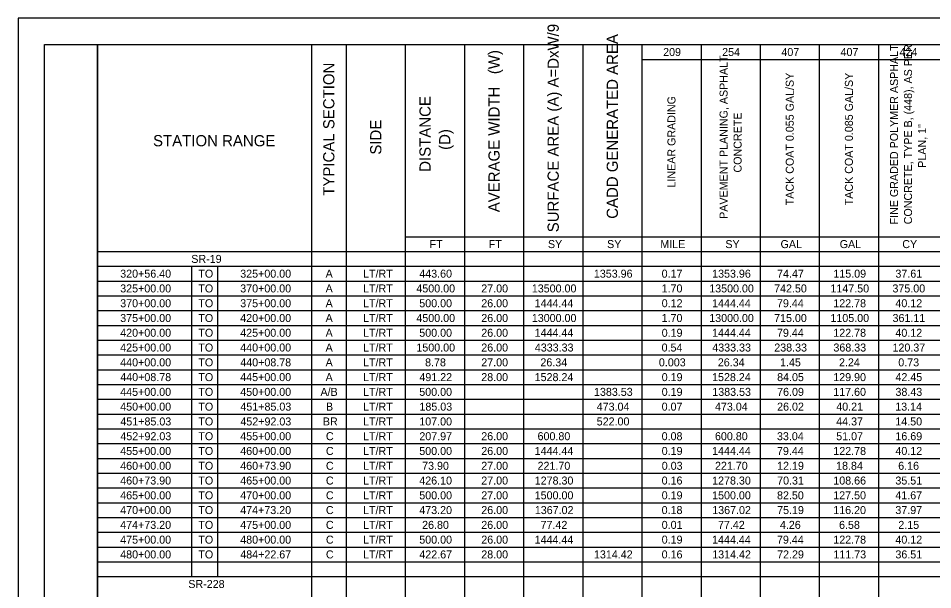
# Model space of a CAD drawing. Extents: x 0 to 34, y 0 to 22.
# Drawn here: x 0 to 17.33, y 11.16 to 22 of the extents above; entities that cross this region are included whole.
import ezdxf

# ---------------------------------------------------------------- set-up
doc = ezdxf.new("R2010")
doc.units = 0
for name, color, linetype in [('SH_Border', 7, 'Continuous'), ('SH_Cut_Line', 7, 'Continuous'), ('SH_Text', 7, 'Continuous')]:
    doc.layers.add(name, color=color, linetype=linetype)

msp = doc.modelspace()

# ---------------------------------------------------------------- linework, layer by layer
at = {"layer": 'SH_Border'}
for points in [[(0.5, 21.5), (1.5, 21.5), (1.5, 0.5), (0.5, 0.5)], [(1.5, 21.5), (33.5, 21.5), (33.5, 0.5), (1.5, 0.5)]]:
    msp.add_lwpolyline(points, close=True, dxfattribs=at)
at = {"layer": 'SH_Cut_Line'}
msp.add_lwpolyline([(0, 0), (34, 0), (34, 22), (0, 22)], close=True, dxfattribs=at)
at = {"layer": 'SH_Text'}
for p, q in [((1.5, 21.5), (32, 21.5)), ((1.5, 21.5), (1.5, 0.513)), ((5.556, 21.5), (5.556, 1.04)), ((6.215, 21.5), (6.215, 1.04)), ((7.336, 21.5), (7.336, 1.04)), ((8.457, 21.5), (8.457, 1.04)), ((9.578, 21.5), (9.578, 1.04)), ((10.699, 21.5), (10.699, 1.04)), ((11.821, 21.5), (11.821, 0.513)), ((12.942, 21.5), (12.942, 0.513)), ((14.063, 21.5), (14.063, 0.513)), ((15.184, 21.5), (15.184, 0.513)), ((16.305, 21.5), (16.305, 0.513)), ((11.821, 21.22), (32, 21.22)), ((7.336, 17.856), (32, 17.856)), ((1.5, 17.576), (32, 17.576)), ((1.5, 17.296), (32, 17.296)), ((3.281, 17.296), (3.281, 11.41)), ((3.775, 17.296), (3.775, 11.41)), ((1.5, 17.016), (32, 17.016)), ((1.5, 16.735), (32, 16.735)), ((1.5, 16.455), (32, 16.455)), ((1.5, 16.175), (32, 16.175)), ((1.5, 15.895), (32, 15.895)), ((1.5, 15.614), (32, 15.614)), ((1.5, 15.334), (32, 15.334)), ((1.5, 15.054), (32, 15.054)), ((1.5, 14.774), (32, 14.774)), ((1.5, 14.493), (32, 14.493)), ((1.5, 14.213), (32, 14.213)), ((1.5, 13.933), (32, 13.933)), ((1.5, 13.652), (32, 13.652)), ((1.5, 13.372), (32, 13.372)), ((1.5, 13.092), (32, 13.092)), ((1.5, 12.812), (32, 12.812)), ((1.5, 12.531), (32, 12.531)), ((1.5, 12.251), (32, 12.251)), ((1.5, 11.971), (32, 11.971)), ((1.5, 11.691), (32, 11.691)), ((1.5, 11.41), (32, 11.41))]:
    msp.add_line(p, q, dxfattribs=at)

# ---------------------------------------------------------------- texts
for s, height, p in [('SURFACE AREA (A) A=DxW/9', 0.21235, (10.245, 17.941)), ('CADD GENERATED AREA', 0.21235, (11.366, 18.197)), ('FINE GRADED POLYMER ASPHALT ', 0.15168, (16.676, 18.09)), ('CONCRETE, TYPE B, (448), AS PER ', 0.15168, (16.941, 18.092)), ('AVERAGE WIDTH   (W)', 0.21235, (9.124, 18.321)), ('PAVEMENT PLANING, ASPHALT ', 0.15168, (13.445, 18.196)), ('TYPICAL SECTION', 0.21235, (5.992, 18.634)), ('TACK COAT 0.055 GAL/SY', 0.15168, (14.699, 18.453)), ('TACK COAT 0.085 GAL/SY', 0.15168, (15.82, 18.453)), ('DISTANCE                                                                                                        ', 0.212346, (7.817, 19.088)), ('LINEAR GRADING', 0.15168, (12.457, 18.789)), ('CONCRETE', 0.1517, (13.711, 19.074)), ('SIDE', 0.2123, (6.882, 19.413)), ('PLAN, 1"', 0.1517, (17.207, 19.165)), ('(D)', 0.2123, (8.189, 19.504))]:
    msp.add_text(s, height=height, rotation=90, dxfattribs=at).set_placement(p)
for s, height, p in [('209', 0.1517, (12.223, 21.284)), ('254', 0.1517, (13.342, 21.284)), ('407', 0.1517, (14.465, 21.284)), ('407', 0.1517, (15.586, 21.284)), ('424', 0.1517, (16.705, 21.284)), ('STATION RANGE', 0.21235, (2.554, 19.572)), ('FT', 0.1517, (7.796, 17.641)), ('FT', 0.1517, (8.917, 17.641)), ('SY', 0.1517, (10.04, 17.641)), ('SY', 0.1517, (11.161, 17.641)), ('MILE', 0.1517, (12.17, 17.641)), ('SY', 0.1517, (13.403, 17.641)), ('GAL', 0.1517, (14.449, 17.641)), ('GAL', 0.1517, (15.57, 17.641)), ('CY', 0.1517, (16.757, 17.641)), ('SR-19', 0.1517, (3.279, 17.36)), ('320+56.40', 0.1517, (1.932, 17.08)), ('TO', 0.1517, (3.413, 17.08)), ('325+00.00', 0.1517, (4.207, 17.08)), ('A', 0.152, (5.825, 17.08)), ('LT/RT', 0.1517, (6.535, 17.08)), ('443.60', 0.1517, (7.601, 17.08)), ('1353.96', 0.1517, (10.91, 17.08)), ('0.17', 0.1517, (12.195, 17.08)), ('1353.96', 0.1517, (13.152, 17.08)), ('74.47', 0.1517, (14.383, 17.08)), ('115.09', 0.1517, (15.45, 17.08)), ('37.61', 0.1517, (16.626, 17.08)), ('325+00.00', 0.1517, (1.932, 16.8)), ('TO', 0.1517, (3.413, 16.8)), ('370+00.00', 0.1517, (4.207, 16.8)), ('A', 0.152, (5.825, 16.8)), ('LT/RT', 0.1517, (6.535, 16.8)), ('4500.00', 0.1517, (7.546, 16.8)), ('27.00', 0.1517, (8.776, 16.8)), ('13500.00', 0.1517, (9.734, 16.8)), ('1.70', 0.1517, (12.194, 16.8)), ('13500.00', 0.1517, (13.097, 16.8)), ('742.50', 0.1517, (14.327, 16.8)), ('1147.50', 0.1517, (15.394, 16.8)), ('375.00', 0.1517, (16.57, 16.8)), ('370+00.00', 0.1517, (1.932, 16.519)), ('TO', 0.1517, (3.413, 16.519)), ('375+00.00', 0.1517, (4.207, 16.519)), ('A', 0.152, (5.825, 16.519)), ('LT/RT', 0.1517, (6.535, 16.519)), ('500.00', 0.1517, (7.601, 16.519)), ('26.00', 0.1517, (8.776, 16.519)), ('1444.44', 0.1517, (9.788, 16.519)), ('0.12', 0.1517, (12.196, 16.519)), ('1444.44', 0.1517, (13.151, 16.519)), ('79.44', 0.1517, (14.381, 16.519)), ('122.78', 0.1517, (15.449, 16.519)), ('40.12', 0.1517, (16.626, 16.519)), ('375+00.00', 0.1517, (1.932, 16.239)), ('TO', 0.1517, (3.413, 16.239)), ('420+00.00', 0.1517, (4.207, 16.239)), ('A', 0.152, (5.825, 16.239)), ('LT/RT', 0.1517, (6.535, 16.239)), ('4500.00', 0.1517, (7.546, 16.239)), ('26.00', 0.1517, (8.776, 16.239)), ('13000.00', 0.1517, (9.734, 16.239)), ('1.70', 0.1517, (12.194, 16.239)), ('13000.00', 0.1517, (13.097, 16.239)), ('715.00', 0.1517, (14.327, 16.239)), ('1105.00', 0.1517, (15.394, 16.239)), ('361.11', 0.1517, (16.572, 16.239)), ('420+00.00', 0.1517, (1.932, 15.959)), ('TO', 0.1517, (3.413, 15.959)), ('425+00.00', 0.1517, (4.207, 15.959)), ('A', 0.152, (5.825, 15.959)), ('LT/RT', 0.1517, (6.535, 15.959)), ('500.00', 0.1517, (7.601, 15.959)), ('26.00', 0.1517, (8.776, 15.959)), ('1444.44', 0.1517, (9.788, 15.959)), ('0.19', 0.1517, (12.196, 15.959)), ('1444.44', 0.1517, (13.151, 15.959)), ('79.44', 0.1517, (14.381, 15.959)), ('122.78', 0.1517, (15.449, 15.959)), ('40.12', 0.1517, (16.626, 15.959)), ('425+00.00', 0.1517, (1.932, 15.679)), ('TO', 0.1517, (3.413, 15.679)), ('440+00.00', 0.1517, (4.207, 15.679)), ('A', 0.152, (5.825, 15.679)), ('LT/RT', 0.1517, (6.535, 15.679)), ('1500.00', 0.1517, (7.546, 15.679)), ('26.00', 0.1517, (8.776, 15.679)), ('4333.33', 0.1517, (9.791, 15.679)), ('0.54', 0.1517, (12.194, 15.679)), ('4333.33', 0.1517, (13.155, 15.679)), ('238.33', 0.1517, (14.33, 15.679)), ('368.33', 0.1517, (15.451, 15.679)), ('120.37', 0.1517, (16.571, 15.679)), ('440+00.00', 0.1517, (1.932, 15.398)), ('TO', 0.1517, (3.413, 15.398)), ('440+08.78', 0.1517, (4.208, 15.398)), ('A', 0.152, (5.825, 15.398)), ('LT/RT', 0.1517, (6.535, 15.398)), ('8.78', 0.1517, (7.711, 15.398)), ('27.00', 0.1517, (8.776, 15.398)), ('26.34', 0.1517, (9.897, 15.398)), ('0.003', 0.1517, (12.143, 15.398)), ('26.34', 0.1517, (13.26, 15.398)), ('1.45', 0.1517, (14.439, 15.398)), ('2.24', 0.1517, (15.557, 15.398)), ('0.73', 0.1517, (16.681, 15.398)), ('440+08.78', 0.1517, (1.933, 15.118)), ('TO', 0.1517, (3.413, 15.118)), ('445+00.00', 0.1517, (4.207, 15.118)), ('A', 0.152, (5.825, 15.118)), ('LT/RT', 0.1517, (6.535, 15.118)), ('491.22', 0.1517, (7.603, 15.118)), ('28.00', 0.1517, (8.776, 15.118)), ('1528.24', 0.1517, (9.788, 15.118)), ('0.19', 0.1517, (12.196, 15.118)), ('1528.24', 0.1517, (13.151, 15.118)), ('84.05', 0.1517, (14.384, 15.118)), ('129.90', 0.1517, (15.448, 15.118)), ('42.45', 0.1517, (16.627, 15.118)), ('445+00.00', 0.1517, (1.932, 14.838)), ('TO', 0.1517, (3.413, 14.838)), ('450+00.00', 0.1517, (4.207, 14.838)), ('A/B', 0.1517, (5.728, 14.838)), ('LT/RT', 0.1517, (6.535, 14.838)), ('500.00', 0.1517, (7.601, 14.838)), ('1383.53', 0.1517, (10.913, 14.838)), ('0.19', 0.1517, (12.196, 14.838)), ('1383.53', 0.1517, (13.155, 14.838)), ('76.09', 0.1517, (14.384, 14.838)), ('117.60', 0.1517, (15.448, 14.838)), ('38.43', 0.1517, (16.627, 14.838)), ('450+00.00', 0.1517, (1.932, 14.558)), ('TO', 0.1517, (3.413, 14.558)), ('451+85.03', 0.1517, (4.21, 14.558)), ('B', 0.152, (5.832, 14.558)), ('LT/RT', 0.1517, (6.535, 14.558)), ('185.03', 0.1517, (7.604, 14.558)), ('473.04', 0.1517, (10.964, 14.558)), ('0.07', 0.1517, (12.195, 14.558)), ('473.04', 0.1517, (13.206, 14.558)), ('26.02', 0.1517, (14.384, 14.558)), ('40.21', 0.1517, (15.505, 14.558)), ('13.14', 0.1517, (16.623, 14.558)), ('451+85.03', 0.1517, (1.935, 14.277)), ('TO', 0.1517, (3.413, 14.277)), ('452+92.03', 0.1517, (4.21, 14.277)), ('BR', 0.1517, (5.773, 14.277)), ('LT/RT', 0.1517, (6.535, 14.277)), ('107.00', 0.1517, (7.601, 14.277)), ('522.00', 0.1517, (10.964, 14.277)), ('44.37', 0.1517, (15.504, 14.277)), ('14.50', 0.1517, (16.624, 14.277)), ('452+92.03', 0.1517, (1.935, 13.997)), ('TO', 0.1517, (3.413, 13.997)), ('455+00.00', 0.1517, (4.207, 13.997)), ('C', 0.152, (5.831, 13.997)), ('LT/RT', 0.1517, (6.535, 13.997)), ('207.97', 0.1517, (7.602, 13.997)), ('26.00', 0.1517, (8.776, 13.997)), ('600.80', 0.1517, (9.843, 13.997)), ('0.08', 0.1517, (12.195, 13.997)), ('600.80', 0.1517, (13.206, 13.997)), ('33.04', 0.1517, (14.381, 13.997)), ('51.07', 0.1517, (15.504, 13.997)), ('16.69', 0.1517, (16.626, 13.997)), ('455+00.00', 0.1517, (1.932, 13.717)), ('TO', 0.1517, (3.413, 13.717)), ('460+00.00', 0.1517, (4.207, 13.717)), ('C', 0.152, (5.831, 13.717)), ('LT/RT', 0.1517, (6.535, 13.717)), ('500.00', 0.1517, (7.601, 13.717)), ('26.00', 0.1517, (8.776, 13.717)), ('1444.44', 0.1517, (9.788, 13.717)), ('0.19', 0.1517, (12.196, 13.717)), ('1444.44', 0.1517, (13.151, 13.717)), ('79.44', 0.1517, (14.381, 13.717)), ('122.78', 0.1517, (15.449, 13.717)), ('40.12', 0.1517, (16.626, 13.717)), ('460+00.00', 0.1517, (1.932, 13.436)), ('TO', 0.1517, (3.413, 13.436)), ('460+73.90', 0.1517, (4.207, 13.436)), ('C', 0.152, (5.831, 13.436)), ('LT/RT', 0.1517, (6.535, 13.436)), ('73.90', 0.1517, (7.655, 13.436)), ('27.00', 0.1517, (8.776, 13.436)), ('221.70', 0.1517, (9.843, 13.436)), ('0.03', 0.1517, (12.197, 13.436)), ('221.70', 0.1517, (13.206, 13.436)), ('12.19', 0.1517, (14.384, 13.436)), ('18.84', 0.1517, (15.502, 13.436)), ('6.16', 0.1517, (16.679, 13.436)), ('460+73.90', 0.1517, (1.932, 13.156)), ('TO', 0.1517, (3.413, 13.156)), ('465+00.00', 0.1517, (4.207, 13.156)), ('C', 0.152, (5.831, 13.156)), ('LT/RT', 0.1517, (6.535, 13.156)), ('426.10', 0.1517, (7.601, 13.156)), ('27.00', 0.1517, (8.776, 13.156)), ('1278.30', 0.1517, (9.789, 13.156)), ('0.16', 0.1517, (12.195, 13.156)), ('1278.30', 0.1517, (13.152, 13.156)), ('70.31', 0.1517, (14.384, 13.156)), ('108.66', 0.1517, (15.449, 13.156)), ('35.51', 0.1517, (16.626, 13.156)), ('465+00.00', 0.1517, (1.932, 12.876)), ('TO', 0.1517, (3.413, 12.876)), ('470+00.00', 0.1517, (4.207, 12.876)), ('C', 0.152, (5.831, 12.876)), ('LT/RT', 0.1517, (6.535, 12.876)), ('500.00', 0.1517, (7.601, 12.876)), ('27.00', 0.1517, (8.776, 12.876)), ('1500.00', 0.1517, (9.789, 12.876)), ('0.19', 0.1517, (12.196, 12.876)), ('1500.00', 0.1517, (13.152, 12.876)), ('82.50', 0.1517, (14.382, 12.876)), ('127.50', 0.1517, (15.448, 12.876)), ('41.67', 0.1517, (16.625, 12.876)), ('470+00.00', 0.1517, (1.932, 12.596)), ('TO', 0.1517, (3.413, 12.596)), ('474+73.20', 0.1517, (4.207, 12.596)), ('C', 0.152, (5.831, 12.596)), ('LT/RT', 0.1517, (6.535, 12.596)), ('473.20', 0.1517, (7.601, 12.596)), ('26.00', 0.1517, (8.776, 12.596)), ('1367.02', 0.1517, (9.791, 12.596)), ('0.18', 0.1517, (12.195, 12.596)), ('1367.02', 0.1517, (13.154, 12.596)), ('75.19', 0.1517, (14.384, 12.596)), ('116.20', 0.1517, (15.448, 12.596)), ('37.97', 0.1517, (16.625, 12.596)), ('474+73.20', 0.1517, (1.932, 12.315)), ('TO', 0.1517, (3.413, 12.315)), ('475+00.00', 0.1517, (4.207, 12.315)), ('C', 0.152, (5.831, 12.315)), ('LT/RT', 0.1517, (6.535, 12.315)), ('26.80', 0.1517, (7.655, 12.315)), ('26.00', 0.1517, (8.776, 12.315)), ('77.42', 0.1517, (9.9, 12.315)), ('0.01', 0.1517, (12.196, 12.315)), ('77.42', 0.1517, (13.263, 12.315)), ('4.26', 0.1517, (14.437, 12.315)), ('6.58', 0.1517, (15.558, 12.315)), ('2.15', 0.1517, (16.681, 12.315)), ('475+00.00', 0.1517, (1.932, 12.035)), ('TO', 0.1517, (3.413, 12.035)), ('480+00.00', 0.1517, (4.207, 12.035)), ('C', 0.152, (5.831, 12.035)), ('LT/RT', 0.1517, (6.535, 12.035)), ('500.00', 0.1517, (7.601, 12.035)), ('26.00', 0.1517, (8.776, 12.035)), ('1444.44', 0.1517, (9.788, 12.035)), ('0.19', 0.1517, (12.196, 12.035)), ('1444.44', 0.1517, (13.151, 12.035)), ('79.44', 0.1517, (14.381, 12.035)), ('122.78', 0.1517, (15.449, 12.035)), ('40.12', 0.1517, (16.626, 12.035)), ('480+00.00', 0.1517, (1.932, 11.755)), ('TO', 0.1517, (3.413, 11.755)), ('484+22.67', 0.1517, (4.208, 11.755)), ('C', 0.152, (5.831, 11.755)), ('LT/RT', 0.1517, (6.535, 11.755)), ('422.67', 0.1517, (7.602, 11.755)), ('28.00', 0.1517, (8.776, 11.755)), ('1314.42', 0.1517, (10.912, 11.755)), ('0.16', 0.1517, (12.195, 11.755)), ('1314.42', 0.1517, (13.154, 11.755)), ('72.29', 0.1517, (14.384, 11.755)), ('111.73', 0.1517, (15.451, 11.755)), ('36.51', 0.1517, (16.626, 11.755)), ('SR-228', 0.1517, (3.223, 11.194))]:
    msp.add_text(s, height=height, dxfattribs=at).set_placement(p)

doc.saveas('drawing.dxf')
